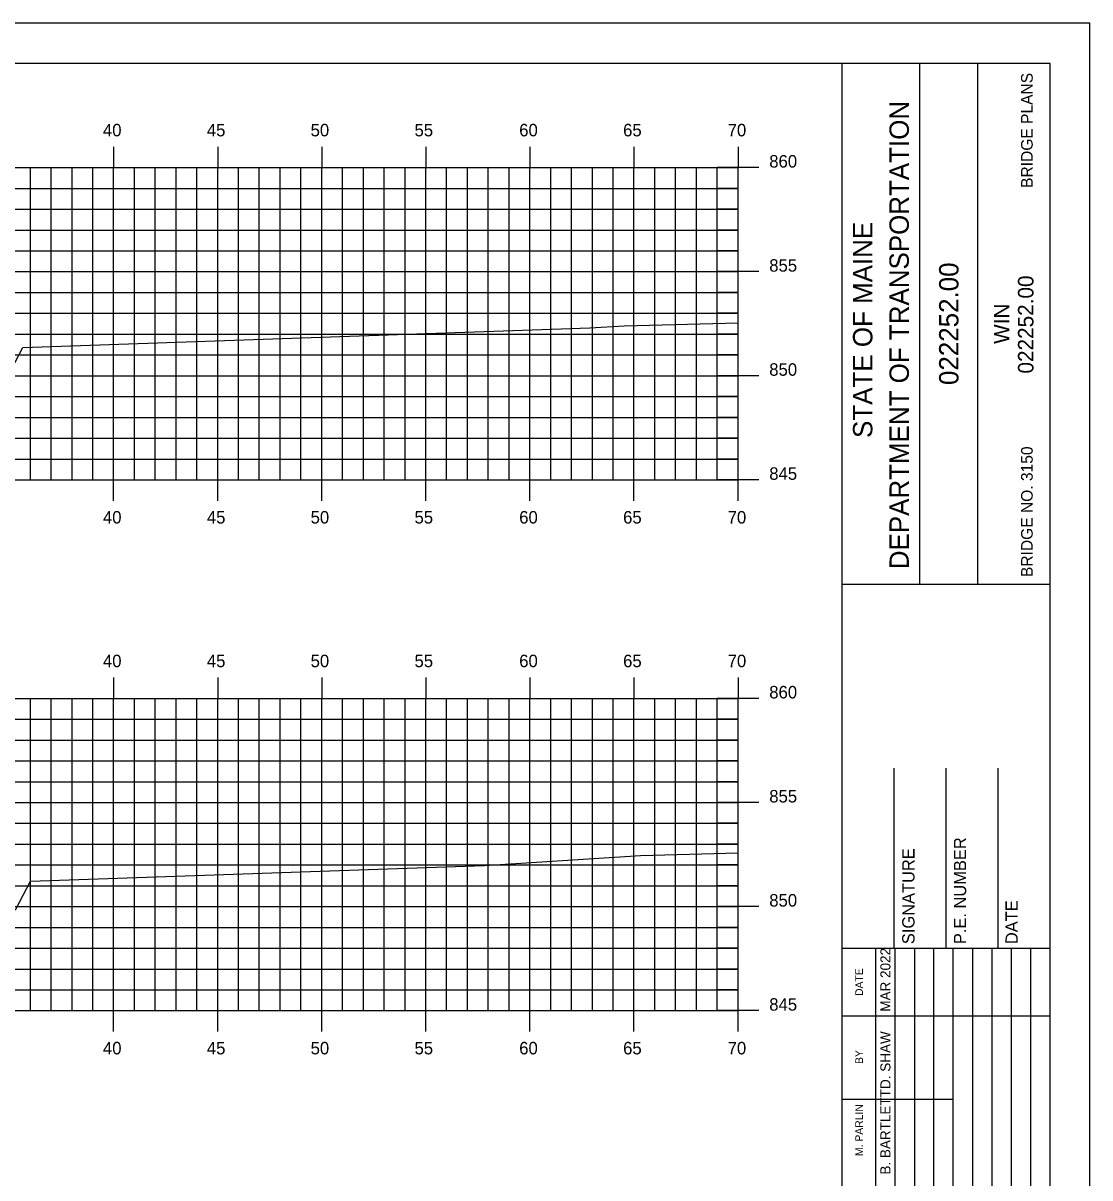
# Model space of a CAD drawing. Extents: x 2193811 to 2194294, y 863888 to 863998.
# Drawn here: x 2194068.9 to 2194120.1, y 863942.9 to 863998.4 of the extents above; entities that cross this region are included whole.
import ezdxf

# ---------------------------------------------------------------- set-up
doc = ezdxf.new("R2010")
doc.units = 0
for name, color, linetype in [('BORDER', 7, 'Continuous'), ('BRIDGE_TITLE', 7, 'Continuous'), ('H_V ANNOTATION', 7, 'Continuous'), ('MAJOR', 7, 'Continuous'), ('MINOR', 7, 'Continuous'), ('PLOT BOUNDARY', 7, 'Continuous'), ('S_Roadway_Centerline', 7, 'Continuous')]:
    doc.layers.add(name, color=color, linetype=linetype)

msp = doc.modelspace()

# ---------------------------------------------------------------- linework, layer by layer
at = {"layer": 'BORDER'}
for p, q in [((2194108.23, 863891.446), (2194108.23, 863996.446)), ((2194111.958, 863971.443), (2194111.958, 863996.443)), ((2194114.753, 863971.443), (2194114.753, 863996.443)), ((2194108.231, 863971.44), (2194118.23, 863971.44)), ((2194110.73, 863953.949), (2194110.73, 863962.596)), ((2194113.23, 863953.949), (2194113.23, 863962.596)), ((2194115.73, 863953.949), (2194115.73, 863962.596)), ((2194108.23, 863953.949), (2194118.23, 863953.949))]:
    msp.add_line(p, q, dxfattribs=at)
msp.add_lwpolyline([(2193958.23, 863891.446), (2194118.23, 863891.446), (2194118.23, 863996.446), (2193958.23, 863996.446)], close=True, dxfattribs=at)
for points in [[(2194109.845, 863950.699), (2194109.845, 863953.949)], [(2194110.777, 863936.452), (2194110.777, 863953.949)], [(2194111.709, 863953.949), (2194111.709, 863936.452)], [(2194112.641, 863936.452), (2194112.641, 863953.949)], [(2194113.572, 863936.452), (2194113.572, 863953.949)], [(2194114.504, 863936.452), (2194114.504, 863953.949)], [(2194115.436, 863936.452), (2194115.436, 863953.949)], [(2194116.367, 863936.452), (2194116.367, 863953.949)], [(2194117.299, 863936.452), (2194117.299, 863953.949)], [(2194109.846, 863936.452), (2194109.846, 863953.243)], [(2194108.23, 863950.699), (2194118.23, 863950.699)], [(2194108.23, 863946.699), (2194109.846, 863946.699)], [(2194109.845, 863946.699), (2194113.571, 863946.699)]]:
    msp.add_lwpolyline(points, dxfattribs=at)
at = {"layer": 'MAJOR'}
for p, q in [((2194073.23, 863992.448), (2194073.23, 863991.446)), ((2194078.23, 863992.448), (2194078.23, 863991.446)), ((2194083.23, 863992.448), (2194083.23, 863991.446)), ((2194088.23, 863992.448), (2194088.23, 863991.446)), ((2194093.23, 863992.448), (2194093.23, 863991.446)), ((2194098.23, 863992.448), (2194098.23, 863991.446)), ((2194103.23, 863992.448), (2194103.23, 863991.446)), ((2193963.23, 863991.446), (2194103.23, 863991.446)), ((2193963.23, 863991.446), (2194103.23, 863991.446)), ((2194073.23, 863976.446), (2194073.23, 863991.446)), ((2194078.23, 863976.446), (2194078.23, 863991.446)), ((2194083.23, 863976.446), (2194083.23, 863991.446)), ((2194088.23, 863976.446), (2194088.23, 863991.446)), ((2194093.23, 863976.446), (2194093.23, 863991.446)), ((2194098.23, 863976.446), (2194098.23, 863991.446)), ((2194104.232, 863991.446), (2194102.228, 863991.446)), ((2194103.23, 863976.446), (2194103.23, 863991.446)), ((2194103.23, 863976.446), (2194103.23, 863991.446)), ((2193963.23, 863986.446), (2194103.23, 863986.446)), ((2194104.232, 863986.446), (2194102.228, 863986.446)), ((2193963.23, 863981.446), (2194103.23, 863981.446)), ((2194104.232, 863981.446), (2194102.228, 863981.446)), ((2193963.23, 863976.446), (2194103.23, 863976.446)), ((2194073.23, 863975.444), (2194073.23, 863976.446)), ((2194078.23, 863975.444), (2194078.23, 863976.446)), ((2194083.23, 863975.444), (2194083.23, 863976.446)), ((2194088.23, 863975.444), (2194088.23, 863976.446)), ((2194093.23, 863975.444), (2194093.23, 863976.446)), ((2194098.23, 863975.444), (2194098.23, 863976.446)), ((2194104.232, 863976.446), (2194102.228, 863976.446)), ((2194103.23, 863975.444), (2194103.23, 863976.446)), ((2194073.23, 863966.948), (2194073.23, 863965.946)), ((2194078.23, 863966.948), (2194078.23, 863965.946)), ((2194083.23, 863966.948), (2194083.23, 863965.946)), ((2194088.23, 863966.948), (2194088.23, 863965.946)), ((2194093.23, 863966.948), (2194093.23, 863965.946)), ((2194098.23, 863966.948), (2194098.23, 863965.946)), ((2194103.23, 863966.948), (2194103.23, 863965.946)), ((2193963.23, 863965.946), (2194103.23, 863965.946)), ((2193963.23, 863965.946), (2194103.23, 863965.946)), ((2194073.23, 863950.946), (2194073.23, 863965.946)), ((2194078.23, 863950.946), (2194078.23, 863965.946)), ((2194083.23, 863950.946), (2194083.23, 863965.946)), ((2194088.23, 863950.946), (2194088.23, 863965.946)), ((2194093.23, 863950.946), (2194093.23, 863965.946)), ((2194098.23, 863950.946), (2194098.23, 863965.946)), ((2194104.232, 863965.946), (2194102.228, 863965.946)), ((2194103.23, 863950.946), (2194103.23, 863965.946)), ((2194103.23, 863950.946), (2194103.23, 863965.946)), ((2193963.23, 863960.946), (2194103.23, 863960.946)), ((2194104.232, 863960.946), (2194102.228, 863960.946)), ((2193963.23, 863955.946), (2194103.23, 863955.946)), ((2194104.232, 863955.946), (2194102.228, 863955.946)), ((2193963.23, 863950.946), (2194103.23, 863950.946)), ((2194073.23, 863949.944), (2194073.23, 863950.946)), ((2194078.23, 863949.944), (2194078.23, 863950.946)), ((2194083.23, 863949.944), (2194083.23, 863950.946)), ((2194088.23, 863949.944), (2194088.23, 863950.946)), ((2194093.23, 863949.944), (2194093.23, 863950.946)), ((2194098.23, 863949.944), (2194098.23, 863950.946)), ((2194104.232, 863950.946), (2194102.228, 863950.946)), ((2194103.23, 863949.944), (2194103.23, 863950.946))]:
    msp.add_line(p, q, dxfattribs=at)
at = {"layer": 'MINOR'}
for p, q in [((2194069.23, 863976.446), (2194069.23, 863991.446)), ((2194070.23, 863976.446), (2194070.23, 863991.446)), ((2194071.23, 863976.446), (2194071.23, 863991.446)), ((2194072.23, 863976.446), (2194072.23, 863991.446)), ((2194074.23, 863976.446), (2194074.23, 863991.446)), ((2194075.23, 863976.446), (2194075.23, 863991.446)), ((2194076.23, 863976.446), (2194076.23, 863991.446)), ((2194077.23, 863976.446), (2194077.23, 863991.446)), ((2194079.23, 863976.446), (2194079.23, 863991.446)), ((2194080.23, 863976.446), (2194080.23, 863991.446)), ((2194081.23, 863976.446), (2194081.23, 863991.446)), ((2194082.23, 863976.446), (2194082.23, 863991.446)), ((2194084.23, 863976.446), (2194084.23, 863991.446)), ((2194085.23, 863976.446), (2194085.23, 863991.446)), ((2194086.23, 863976.446), (2194086.23, 863991.446)), ((2194087.23, 863976.446), (2194087.23, 863991.446)), ((2194089.23, 863976.446), (2194089.23, 863991.446)), ((2194090.23, 863976.446), (2194090.23, 863991.446)), ((2194091.23, 863976.446), (2194091.23, 863991.446)), ((2194092.23, 863976.446), (2194092.23, 863991.446)), ((2194094.23, 863976.446), (2194094.23, 863991.446)), ((2194095.23, 863976.446), (2194095.23, 863991.446)), ((2194096.23, 863976.446), (2194096.23, 863991.446)), ((2194097.23, 863976.446), (2194097.23, 863991.446)), ((2194099.23, 863976.446), (2194099.23, 863991.446)), ((2194100.23, 863976.446), (2194100.23, 863991.446)), ((2194101.23, 863976.446), (2194101.23, 863991.446)), ((2194102.23, 863976.446), (2194102.23, 863991.446)), ((2193963.23, 863990.446), (2194103.23, 863990.446)), ((2194103.23, 863990.446), (2194102.228, 863990.446)), ((2193963.23, 863989.446), (2194103.23, 863989.446)), ((2194103.23, 863989.446), (2194102.228, 863989.446)), ((2193963.23, 863988.446), (2194103.23, 863988.446)), ((2194103.23, 863988.446), (2194102.228, 863988.446)), ((2193963.23, 863987.446), (2194103.23, 863987.446)), ((2194103.23, 863987.446), (2194102.228, 863987.446)), ((2193963.23, 863985.446), (2194103.23, 863985.446)), ((2194103.23, 863985.446), (2194102.228, 863985.446)), ((2193963.23, 863984.446), (2194103.23, 863984.446)), ((2194103.23, 863984.446), (2194102.228, 863984.446)), ((2193963.23, 863983.446), (2194103.23, 863983.446)), ((2194103.23, 863983.446), (2194102.228, 863983.446)), ((2193963.23, 863982.446), (2194103.23, 863982.446)), ((2194103.23, 863982.446), (2194102.228, 863982.446)), ((2193963.23, 863980.446), (2194103.23, 863980.446)), ((2194103.23, 863980.446), (2194102.228, 863980.446)), ((2193963.23, 863979.446), (2194103.23, 863979.446)), ((2194103.23, 863979.446), (2194102.228, 863979.446)), ((2193963.23, 863978.446), (2194103.23, 863978.446)), ((2194103.23, 863978.446), (2194102.228, 863978.446)), ((2193963.23, 863977.446), (2194103.23, 863977.446)), ((2194103.23, 863977.446), (2194102.228, 863977.446)), ((2194069.23, 863950.946), (2194069.23, 863965.946)), ((2194070.23, 863950.946), (2194070.23, 863965.946)), ((2194071.23, 863950.946), (2194071.23, 863965.946)), ((2194072.23, 863950.946), (2194072.23, 863965.946)), ((2194074.23, 863950.946), (2194074.23, 863965.946)), ((2194075.23, 863950.946), (2194075.23, 863965.946)), ((2194076.23, 863950.946), (2194076.23, 863965.946)), ((2194077.23, 863950.946), (2194077.23, 863965.946)), ((2194079.23, 863950.946), (2194079.23, 863965.946)), ((2194080.23, 863950.946), (2194080.23, 863965.946)), ((2194081.23, 863950.946), (2194081.23, 863965.946)), ((2194082.23, 863950.946), (2194082.23, 863965.946)), ((2194084.23, 863950.946), (2194084.23, 863965.946)), ((2194085.23, 863950.946), (2194085.23, 863965.946)), ((2194086.23, 863950.946), (2194086.23, 863965.946)), ((2194087.23, 863950.946), (2194087.23, 863965.946)), ((2194089.23, 863950.946), (2194089.23, 863965.946)), ((2194090.23, 863950.946), (2194090.23, 863965.946)), ((2194091.23, 863950.946), (2194091.23, 863965.946)), ((2194092.23, 863950.946), (2194092.23, 863965.946)), ((2194094.23, 863950.946), (2194094.23, 863965.946)), ((2194095.23, 863950.946), (2194095.23, 863965.946)), ((2194096.23, 863950.946), (2194096.23, 863965.946)), ((2194097.23, 863950.946), (2194097.23, 863965.946)), ((2194099.23, 863950.946), (2194099.23, 863965.946)), ((2194100.23, 863950.946), (2194100.23, 863965.946)), ((2194101.23, 863950.946), (2194101.23, 863965.946)), ((2194102.23, 863950.946), (2194102.23, 863965.946)), ((2193963.23, 863964.946), (2194103.23, 863964.946)), ((2194103.23, 863964.946), (2194102.228, 863964.946)), ((2193963.23, 863963.946), (2194103.23, 863963.946)), ((2194103.23, 863963.946), (2194102.228, 863963.946)), ((2193963.23, 863962.946), (2194103.23, 863962.946)), ((2194103.23, 863962.946), (2194102.228, 863962.946)), ((2193963.23, 863961.946), (2194103.23, 863961.946)), ((2194103.23, 863961.946), (2194102.228, 863961.946)), ((2193963.23, 863959.946), (2194103.23, 863959.946)), ((2194103.23, 863959.946), (2194102.228, 863959.946)), ((2193963.23, 863958.946), (2194103.23, 863958.946)), ((2194103.23, 863958.946), (2194102.228, 863958.946)), ((2193963.23, 863957.946), (2194103.23, 863957.946)), ((2194103.23, 863957.946), (2194102.228, 863957.946)), ((2193963.23, 863956.946), (2194103.23, 863956.946)), ((2194103.23, 863956.946), (2194102.228, 863956.946)), ((2193963.23, 863954.946), (2194103.23, 863954.946)), ((2194103.23, 863954.946), (2194102.228, 863954.946)), ((2193963.23, 863953.946), (2194103.23, 863953.946)), ((2194103.23, 863953.946), (2194102.228, 863953.946)), ((2193963.23, 863952.946), (2194103.23, 863952.946)), ((2194103.23, 863952.946), (2194102.228, 863952.946)), ((2193963.23, 863951.946), (2194103.23, 863951.946)), ((2194103.23, 863951.946), (2194102.228, 863951.946))]:
    msp.add_line(p, q, dxfattribs=at)
at = {"layer": 'PLOT BOUNDARY'}
msp.add_lwpolyline([(2193950.137, 863888.387), (2194120.137, 863888.387), (2194120.137, 863998.387), (2193950.137, 863998.387)], close=True, dxfattribs=at)
at = {"layer": 'S_Roadway_Centerline'}
for points in [[(2194016.557, 863983.055), (2194016.765, 863983.092), (2194018.378, 863983.255), (2194021.489, 863983.44), (2194023.229, 863983.455), (2194033.175, 863983.634), (2194034.877, 863983.638), (2194044.611, 863983.565), (2194049.88, 863983.514), (2194050.405, 863983.486), (2194058.621, 863983.086), (2194059.206, 863982.798), (2194064.04, 863980.357), (2194065.001, 863980.36), (2194066.666, 863980.278), (2194068.305, 863981.729), (2194068.874, 863982.809), (2194096.108, 863983.744), (2194097.763, 863983.85), (2194103.23, 863983.988)], [(2194016.591, 863957.61), (2194017.347, 863957.685), (2194017.573, 863957.739), (2194019.11, 863957.853), (2194020.143, 863957.957), (2194021.474, 863958.036), (2194022.219, 863958.043), (2194033.171, 863958.24), (2194033.91, 863958.242), (2194044.627, 863958.16), (2194049.245, 863958.116), (2194050.311, 863958.103), (2194051.1, 863958.054), (2194059.304, 863957.643), (2194060.075, 863957.316), (2194064.798, 863954.93), (2194065.457, 863954.932), (2194067.414, 863954.836), (2194068.532, 863955.825), (2194069.241, 863957.171), (2194091.052, 863957.92), (2194098.542, 863958.402), (2194103.23, 863958.52)]]:
    msp.add_lwpolyline(points, dxfattribs=at)

# ---------------------------------------------------------------- texts
at = {"layer": 'BORDER'}
for s, height, p in [('DEPARTMENT OF TRANSPORTATION', 0.93176, (2194111.437, 863972.152)), ('STATE OF MAINE', 0.93176, (2194109.685, 863978.458)), ('022252.00', 0.9318, (2194113.822, 863980.999)), ('022252.00', 0.7453, (2194117.425, 863981.551)), ('WIN', 0.7453, (2194116.267, 863982.976)), ('P.E. NUMBER', 0.59055, (2194114.191, 863954.141)), ('SIGNATURE', 0.5906, (2194111.71, 863954.141)), ('DATE', 0.5906, (2194116.671, 863954.141)), ('MAR 2022', 0.4845, (2194110.553, 863950.897)), ('DATE', 0.3714, (2194109.234, 863951.654)), ('D. SHAW', 0.4845, (2194110.553, 863947.184)), ('BY', 0.3714, (2194109.234, 863948.384)), ('B. BARTLETT', 0.48455, (2194110.553, 863943.072)), ('M. PARLIN', 0.3727, (2194109.234, 863943.962))]:
    msp.add_text(s, height=height, rotation=90, dxfattribs=at).set_placement(p)
at = {"layer": 'BRIDGE_TITLE'}
for s, p in [('BRIDGE PLANS', (2194117.388, 863990.47)), ('BRIDGE NO. 3150', (2194117.388, 863971.776))]:
    msp.add_text(s, height=0.55901, rotation=90, dxfattribs=at).set_placement(p)
at = {"layer": 'H_V ANNOTATION'}
for s, p in [('40', (2194072.716, 863992.946)), ('45', (2194077.708, 863992.946)), ('50', (2194082.694, 863992.946)), ('55', (2194087.686, 863992.946)), ('60', (2194092.716, 863992.946)), ('65', (2194097.708, 863992.946)), ('70', (2194102.732, 863992.946)), ('860', (2194104.73, 863991.446)), ('855', (2194104.73, 863986.446)), ('850', (2194104.73, 863981.446)), ('845', (2194104.73, 863976.446)), ('40', (2194072.716, 863974.346)), ('45', (2194077.708, 863974.346)), ('50', (2194082.694, 863974.346)), ('55', (2194087.686, 863974.346)), ('60', (2194092.716, 863974.346)), ('65', (2194097.708, 863974.346)), ('70', (2194102.732, 863974.346)), ('40', (2194072.716, 863967.446)), ('45', (2194077.708, 863967.446)), ('50', (2194082.694, 863967.446)), ('55', (2194087.686, 863967.446)), ('60', (2194092.716, 863967.446)), ('65', (2194097.708, 863967.446)), ('70', (2194102.732, 863967.446)), ('860', (2194104.73, 863965.946)), ('855', (2194104.73, 863960.946)), ('850', (2194104.73, 863955.946)), ('845', (2194104.73, 863950.946)), ('40', (2194072.716, 863948.846)), ('45', (2194077.708, 863948.846)), ('50', (2194082.694, 863948.846)), ('55', (2194087.686, 863948.846)), ('60', (2194092.716, 863948.846)), ('65', (2194097.708, 863948.846)), ('70', (2194102.732, 863948.846))]:
    msp.add_text(s, height=0.6, dxfattribs=at).set_placement(p)

doc.saveas('drawing.dxf')
